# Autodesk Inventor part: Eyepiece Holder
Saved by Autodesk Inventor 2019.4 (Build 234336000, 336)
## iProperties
Created: 2020-09
Part Number: Eyepiece Holder
Material: Generic
Document SubType Name: Modeling
Designer: Administrator
Density: 1 g/cm^3
Appearance: Default
Title: Eyepiece Holder
Author: Administrator
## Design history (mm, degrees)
feature "Body1"
body "Solid1"
